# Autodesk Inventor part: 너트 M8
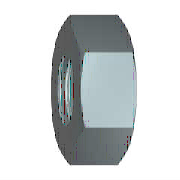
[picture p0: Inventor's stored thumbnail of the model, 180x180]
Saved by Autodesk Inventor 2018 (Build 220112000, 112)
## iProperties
IsCustomPart: 1
Created: 2012-02
Part Number: 너트 M8
Material: 강철, 연강
Description: 6각 너트 및 6각 가는 너트
Document SubType Name: Modeling
Standard: KS B 1012
Designer: mduedu
Standards Organization: KS
Language: ko-KR
Size Designation: M 8
Categories: <MemberInstance><Categories><Category DisplayName="조임쇠" InternalName="e4da775c-781d-43d5-af7c-5136215cf5a6" Mnemonic="FSTN"><Category DisplayName="너트" InternalN
Density: 7.86 g/cm^3
Mass: 4.30432 g
Surface Area: 5.27675 cm^2
Volume: 0.547623 cm^3
Appearance: 강철
Author: mduedu
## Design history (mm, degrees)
sketch "스케치1"
  geometry: L1 (-7.506, 0)-(-3.753, 6.5); L2 (-3.753, 6.5)-(3.753, 6.5); L3 (3.753, 6.5)-(7.506, 0); L4 (7.506, 0)-(3.753, -6.5); L5 (3.753, -6.5)-(-3.753, -6.5); L6 (-3.753, -6.5)-(-7.506, 0); 2 further points
  constraints: 12 end point, 1 coincident, 1 horizontal, 11 other
  dimensions: "d0" = 15.01111 distance of L3.end L1.start (= 1.1547 x SW)
extrude "본체" new body sketch "스케치1" distance "d1" = 5 (= KOH); taper "d2" = 0 deg
sketch "스케치2"
  geometry: L1 (0, 3.753)-(0, 7.506) reference; L2 (0, 7.506)-(5, 7.506) reference; L3 (5, 3.753)-(5, 7.506) reference; L4 (-1, 0)-(6, 0) reference; L5 (0.581, 7.506)-(0, 6.5); L6 (4.419, 7.506)-(5, 6.5)
  constraints: 4 end point, 4 point on line
  dimensions: "d3" = 30 deg angle of L1 L5 (= ANG1); "d4" = 30 deg angle of L3 L6 (= ANG2); "d5" = 13 diameter of L5.end L4 (= SW0); "d6" = 13 diameter of L6.end L4 (= SW01)
revolve "모따기1" sketch "스케치2" stored, may be unused: angle "d7" = 90 deg
sketch "스케치3"
  geometry: A1 r 6.5 centre (0, 0) between (-3.25, -5.629) and (3.25, -5.629) reference; 1 further point
  constraints: 1 coincident
hole "스레드" sketch "스케치3" at (0, 0) diameter "d25" = 6.647; stored, may be unused: countersink angle "d29" = 82 deg, drill point angle "d31" = 118 deg; dims "d26" = 6, "d27" = 4, "d28" = 2, "d30" = 8
workaxis "Work Axis1"
workplane "Work Plane1"
body "Solid1"
chamfer "모따기2" distance "d8" = 0.67658 (= -0.5 x GD1 + 0.5 x NND); stored, may be unused: angle "d9" = 30 deg, second distance "d40" = 0.67658 (= -0.5 x GD1 + 0.5 x NND)
chamfer "모따기3" distance "d10" = 0.67658 (= -0.5 x GD1 + 0.5 x NND); stored, may be unused: angle "d11" = 30 deg, second distance "d41" = 0.67658 (= -0.5 x GD1 + 0.5 x NND)
other parameters: "ANG1" = 30 deg [user parameter; used in 1 equation term], "ANG2" = 30 deg [user parameter; used in 1 equation term], "NND" = 8 [user parameter; used in 4 equation terms], "KOH" = 5 [user parameter; used in 1 equation term], "SW" = 13 [user parameter; used in 4 equation terms], "SW0" = 13 (= SW) [user parameter; used in 1 equation term], "SW01" = 13 (= SW) [user parameter; used in 1 equation term], "GD1" = 6.64684 (computed from THREADDIA, PTC, TOA) [user parameter; used in 4 equation terms], "d13" = 0, "d14" = 0, "d39" = 0, "d42" = 0, "GUL" = 0.67658 (= 0.541266 x PTC) [user parameter], "TPU" = 8 (computed from PTC) [user parameter], "THREADDIA" = 8 [user parameter; used in 1 equation term], "TOA" = 30 deg [user parameter; used in 1 equation term], "PTC" = 1.25 [user parameter; used in 4 equation terms], "E0" = 15.015 (= 1.155 x SW) [user parameter], "GAL" = 0.67658 (= 0.541266 x PTC) [user parameter]
